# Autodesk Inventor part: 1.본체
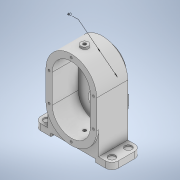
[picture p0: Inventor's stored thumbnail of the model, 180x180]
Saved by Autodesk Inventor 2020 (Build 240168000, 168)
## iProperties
Created: 2021-05
Part Number: 1.본체
Material: 일반
Document SubType Name: Modeling
Designer: Owner
Density: 1 g/cm^3
Appearance: 기본값
Author: Owner
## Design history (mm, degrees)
sketch "스케치1"
  geometry: L1 (0, 62.5)-(0, -62.5); L2 (40, 22.5)-(40, -22.5); L3 (-40, -22.5)-(-40, 22.5); A1 r 40 centre (0, 22.5) between (40, 22.5) and (-40, 22.5); A2 r 40 centre (0, -22.5) between (-40, -22.5) and (40, -22.5); 2 further points
  constraints: 8 end point, 6 point on circle, 4 tangent, 2 centre point, 2 point on line, 1 coincident, 1 midpoint, 1 parallel, 1 vertical
  dimensions: "d4" = 80 distance between parallel lines of L2 L3; "d5" = 45 distance of A2.centre A1.centre
extrude "돌출1" new body sketch "스케치1" distance "d6" = 49; taper "d7" = 0 deg
sketch "스케치2"
  geometry: L1 (0, 52.5)-(0, -52.5); L2 (-30, 22.5)-(-30, -22.5); L3 (30, -22.5)-(30, 22.5); A1 r 30 centre (0, 22.5) between (30, 22.5) and (-30, 22.5); A2 r 30 centre (0, -22.5) between (-30, -22.5) and (30, -22.5); 2 further points
  constraints: 8 end point, 6 point on circle, 4 tangent, 2 centre point, 2 point on line, 1 coincident, 1 midpoint, 1 parallel, 1 vertical
  dimensions: "d9" = 30 radius of A1; "d10" = 45 distance of A2.centre A1.centre
extrude "돌출2" cut sketch "스케치2" distance "d11" = 41; taper "d12" = 0 deg
sketch "스케치3"
  geometry: A1 r 40 centre (0, -22.5) between (-40, -22.5) and (40, -22.5) reference; A2 r 40 centre (0, 22.5) between (40, 22.5) and (-40, 22.5) reference; 1 further point
sketch "스케치4"
  geometry: L1 (-40, -22.5)-(-40, -59.5); L2 (-40, -59.5)-(-61, -59.5); L3 (-61, -59.5)-(-61, -69.5); L4 (-61, -69.5)-(-35, -69.5); L5 (-35, -69.5)-(-35, -64.5); L6 (-35, -64.5)-(0, -64.5); L7 (0, -64.5)-(0, -62.5); A1 r 40 centre (0, -22.5) between (-40, -22.5) and (40, -22.5) reference; 1 further point
  constraints: 14 end point, 6 perpendicular, 1 point on circle, 1 point on line, 1 tangent, 1 vertical
  dimensions: "d20" = 35 distance between parallel lines of L7 L5; "d21" = 10 distance of L2.end L3.end; "d22" = 5 distance between parallel lines of L6 L4; "d23" = 61 distance between parallel lines of L7 L3; "d24" = 47 distance from line of A1.centre L4
extrude "돌출3" join sketch "스케치4" distance "d25" = 46; taper "d26" = 0 deg
sketch "스케치5"
  geometry: L1 (0, 57.5)-(0, -57.5); L2 (-35, 22.5)-(-35, -22.5); L3 (35, -22.5)-(35, 22.5); A1 r 35 centre (0, 22.5) between (35, 22.5) and (-35, 22.5); A2 r 35 centre (0, -22.5) between (-35, -22.5) and (35, -22.5); 6 further points
  constraints: 8 end point, 6 point on circle, 5 coincident, 4 tangent, 2 centre point, 2 point on line, 1 midpoint, 1 parallel, 1 vertical
  dimensions: "d28" = 45 distance of A2.centre A1.centre
hole "구멍1" sketch "스케치5" diameter "d29" = 3.242; stored, may be unused: countersink angle "d33" = 82 deg, drill point angle "d35" = 118 deg; dims "d30" = 8, "d31" = 3.023, "d32" = 2, "d34" = 10
hole "구멍2" sketch "스케치5" diameter "d36" = 3.242; stored, may be unused: countersink angle "d40" = 82 deg, drill point angle "d42" = 118 deg; dims "d37" = 8, "d38" = 3.023, "d39" = 2, "d41" = 10
sketch "스케치6"
  geometry: 1 further point
node "작업 평면1"
sketch "스케치7"
  geometry: L1 (5, 49)-(-75, 49) reference; C1 r 6 at (-35, 28); 1 further point
  constraints: 1 centre point
  dimensions: "d44" = 21 distance from line of L1 C1.centre; "d45" = 12 diameter of C1
extrude "돌출4" join sketch "스케치7" stored distance "d46" = 46; taper "d47" = 0 deg
sketch "스케치8"
  geometry: L1 (-64.5, 0)-(-64.5, 46) reference; L2 (-52.5, 49)-(-22.5, 49) reference; 2 further points
  constraints: 1 point on line
  dimensions: "d48" = 21 distance from line of point (-64.5, 28) L2
sketch "스케치9"
  geometry: C1 r 6 at (-35, 28) reference; 2 further points
  constraints: 1 coincident
hole "구멍3" sketch "스케치9" at (-35, 28) diameter "d49" = 4.917; stored, may be unused: countersink angle "d53" = 82 deg, drill point angle "d55" = 118 deg; dims "d50" = 135, "d51" = 12, "d52" = 1, "d54" = 151.35
sketch "스케치10"
  geometry: L1 (0, 52.5)-(0, -52.5); L2 (-30, 22.5)-(-30, -22.5); L3 (30, -22.5)-(30, 22.5); A1 r 30 centre (0, 22.5) between (30, 22.5) and (-30, 22.5); A2 r 30 centre (0, -22.5) between (-30, -22.5) and (30, -22.5); 2 further points
  constraints: 8 end point, 6 point on circle, 4 tangent, 2 centre point, 2 point on line, 1 coincident, 1 midpoint, 1 parallel, 1 vertical
  dimensions: "d56" = 30 radius of A1; "d57" = 45 distance of A2.centre A1.centre
extrude "돌출5" join sketch "스케치10" distance "d58" = 11; taper "d59" = 0 deg
sketch "스케치11"
  geometry: 1 further point
sketch "스케치12"
  geometry: L1 (21, 0)-(21, -46) reference; L2 (21, -46)-(0, -46) reference; C1 r 5.5 at (11, -36); 1 further point
  constraints: 1 centre point
  dimensions: "d60" = 11 diameter of C1; "d61" = 10 distance from line of L1 C1.centre; "d62" = 10 distance from line of L2 C1.centre
fillet "모깎기1" dims "d63" = 10
sketch "스케치13"
  geometry: L1 (21, 0)-(21, -36) reference; L2 (0, 0)-(21, 0) reference; C1 r 5.5 at (11, -10); 1 further point
  constraints: 1 centre point
  dimensions: "d64" = 11 diameter of C1; "d65" = 10 distance from line of L1 C1.centre; "d66" = 10 distance from line of C1.centre L2
extrude "돌출6" cut sketch "스케치13" distance "d67" = 2; taper "d68" = 0 deg
extrude "돌출7" cut sketch "스케치12" distance "d69" = 2; taper "d70" = 0 deg
fillet "모깎기2" dims "d71" = 10
sketch "스케치14"
  geometry: L1 (-51, -69.5)-(-35, -69.5) reference; C1 r 14 at (0, 22.5); 1 further point
  constraints: 1 centre point, 1 vertical alignment
  dimensions: "d72" = 92 distance from line of L1 C1.centre; "d73" = 28 diameter of C1
extrude "돌출8" cut sketch "스케치14" distance "d74" = 7; taper "d75" = 0 deg
sketch "스케치15"
  geometry: L1 (51, -92)-(35, -92) reference; L2 (-40, 0)-(-40, -82) reference; L3 (-35, -92)-(-35, -87) reference; C1 r 11 at (0, 0); 1 further point
  constraints: 1 centre point
  dimensions: "d76" = 22 diameter of C1; "d77" = 92 distance from line of C1.centre L1; "d79" = 35 distance from line of L3 C1.centre
extrude "돌출9" cut sketch "스케치15" stored distance "d80" = 4; taper "d81" = 0 deg
sketch "스케치16"
  geometry: 1 further point
sketch "스케치17"
  geometry: C1 r 11 at (0, 22.5) reference; C2 r 14 at (0, 22.5); 1 further point
  constraints: 1 centre point, 1 coincident
  dimensions: "d82" = 28 diameter of C2
extrude "돌출10" cut sketch "스케치17" distance "d83" = 8; taper "d84" = 0 deg
sketch "스케치18"
  geometry: C1 r 14 at (0, -22.5); 1 further point
  constraints: 1 centre point
  dimensions: "d85" = 28 diameter of C1; "d86" = 22.5 distance of point (0, 0) C1.centre
extrude "돌출11" cut sketch "스케치18" distance "d87" = 8; taper "d88" = 0 deg
sketch "스케치19"
  geometry: C1 r 10 at (0, 0); 1 further point
  constraints: 1 centre point
  dimensions: "d89" = 20 diameter of C1
extrude "돌출12" cut sketch "스케치19" distance "d90" = 4; taper "d91" = 0 deg
sketch "스케치20"
  geometry: 1 further point
sketch "스케치21"
  geometry: 1 further point
sketch "스케치22"
  geometry: L1 (30, -22.5)-(30, 22.5) reference; L2 (-30, 22.5)-(-30, -22.5) reference; L3 (-30, 22.5)-(-30, -22.5) reference; L4 (-30, -7.5)-(30, -7.5); C1 r 14 at (0, 22.5) reference; A1 r 30 centre (0, 22.5) between (30, 22.5) and (-30, 22.5) reference; 2 further points
  constraints: 2 end point, 2 point on line, 1 perpendicular
  dimensions: "d92" = 30 distance from line of A1.centre L4
extrude "돌출13" cut sketch "스케치22" distance "d93" = 3; taper "d94" = 0 deg
sketch "스케치23"
  geometry: C1 r 11 at (0, 22.5) reference; C2 r 20 at (0, 22.5); 1 further point
  constraints: 1 centre point, 1 coincident
  dimensions: "d95" = 40 diameter of C2
node "솔리드1"
mirror "미러1"
mirror "미러2"
mirror "미러3"
mirror "미러4"
mirror "미러5"
feature "A9D066F2-1C7D-4E18-AEED-F7BC21143FA4" dims "d49" = 4.917, "d50" = 135, "d51" = 12, "d52" = 1, "d53" = 82 deg, "d54" = 151.35, "d55" = 118 deg
